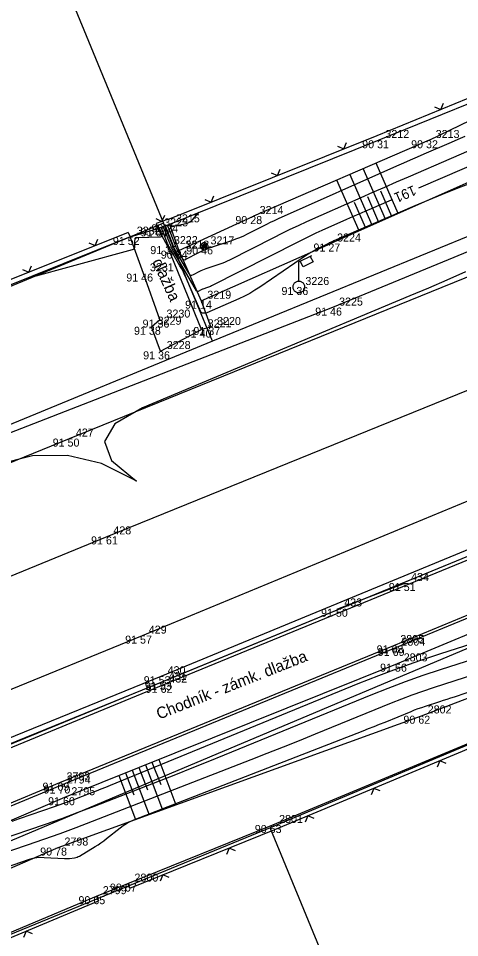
# Model space of a CAD drawing. Extents: x -711081 to -709338, y -1025122 to -1024092.
# Drawn here: x -710242.65 to -710227.21, y -1024728.91 to -1024696.77 of the extents above; entities that cross this region are included whole.
import ezdxf

# ---------------------------------------------------------------- set-up
doc = ezdxf.new("R2010")
doc.units = 0
for name, color, linetype in [('Ex_Contour Labels', 7, 'Continuous'), ('Ex_Major Contours', 7, 'Continuous'), ('Ex_Minor Contours', 7, 'Continuous'), ('Z_betonova_konstrukce', 7, 'Continuous'), ('Z_body', 7, 'Continuous'), ('Z_body_cisla', 7, 'Continuous'), ('Z_body_vysky_redukovane', 7, 'Continuous'), ('Z_chodnik', 7, 'Continuous'), ('Z_hrany_paty', 7, 'Continuous'), ('Z_katastr_hranice', 7, 'Continuous'), ('Z_komunikace', 7, 'Continuous'), ('Z_komunikace_osa', 7, 'Continuous'), ('Z_obruba', 7, 'Continuous'), ('Z_ploty', 7, 'Continuous'), ('Z_ploty_znacky', 7, 'Continuous'), ('Z_popisy', 7, 'Continuous'), ('Z_rozhranni', 7, 'Continuous'), ('Z_site_vo_znaky', 7, 'Continuous'), ('Z_sloupy', 7, 'Continuous'), ('Z_technicke_srafy', 7, 'Continuous'), ('Z_vdz12_plna', 7, 'Continuous'), ('Z_vdz25_plna', 7, 'Continuous'), ('Z_vstupy', 7, 'Continuous'), ('Z_zlabek', 7, 'Continuous')]:
    doc.layers.add(name, color=color, linetype=linetype)

# ---------------------------------------------------------------- blocks, each defined once
blk = doc.blocks.new('POINT_DISPLAY')
blk.add_line((0, 0), (0, 0))
blk = doc.blocks.new('Z212')
for p, q in [((-0.17, 0.17), (0, 0)), ((0, 0), (0.17, 0.17))]:
    blk.add_line(p, q)
blk = doc.blocks.new('Z13')
for p, q in [((0, 0.88), (0.45, 1.1)), ((0.4, 1.07), (0.5, 0.88)), ((0, 0.2), (0, 0.88)), ((0.15, 0.7), (0.05, 0.9)), ((0.5, 0.88), (0.15, 0.7)), ((-0.2, 0.05), (-0.15, 0.15)), ((-0.2, -0.05), (-0.2, 0.05)), ((-0.15, 0.15), (-0.05, 0.2)), ((-0.05, 0.2), (0.05, 0.2)), ((0.05, 0.2), (0.15, 0.15)), ((0.15, 0.15), (0.2, 0.05)), ((0.2, 0.05), (0.2, -0.05)), ((-0.15, -0.15), (-0.2, -0.05)), ((-0.05, -0.2), (-0.15, -0.15)), ((0.05, -0.2), (-0.05, -0.2)), ((0.15, -0.15), (0.05, -0.2)), ((0.2, -0.05), (0.15, -0.15))]:
    blk.add_line(p, q)
blk = doc.blocks.new('Z601')
for p, q in [((-0.13, 0.03), (-0.1, 0.08)), ((-0.13, -0.03), (-0.13, 0.03)), ((-0.1, 0.08), (-0.08, 0.1)), ((-0.08, 0.1), (-0.03, 0.13)), ((-0.08, 0.05), (-0.08, -0.05)), ((-0.03, 0.13), (0.03, 0.13)), ((-0.03, -0.08), (-0.03, 0.08)), ((-0.03, 0.08), (0.03, 0.08)), ((0.03, 0.13), (0.08, 0.1)), ((0.03, 0.08), (0.03, -0.08)), ((0.08, 0.1), (0.1, 0.08)), ((0.08, -0.05), (0.08, 0.05)), ((0.1, 0.08), (0.13, 0.03)), ((0.13, 0.03), (0.13, -0.03)), ((-0.1, -0.08), (-0.13, -0.03)), ((-0.08, -0.1), (-0.1, -0.08)), ((-0.08, -0.05), (-0.03, -0.08)), ((-0.03, -0.13), (-0.08, -0.1)), ((0.03, -0.13), (-0.03, -0.13)), ((0.03, -0.08), (0.08, -0.05)), ((0.08, -0.1), (0.03, -0.13)), ((0.1, -0.08), (0.08, -0.1)), ((0.13, -0.03), (0.1, -0.08))]:
    blk.add_line(p, q)

msp = doc.modelspace()

# ---------------------------------------------------------------- linework, layer by layer
at = {"layer": 'Ex_Major Contours'}
for points in [[(-710223.86, -1024700.64), (-710228.65, -1024702.71)], [(-710229.614, -1024703.126), (-710230.311, -1024703.428), (-710230.527, -1024703.521), (-710230.742, -1024703.615), (-710230.957, -1024703.71), (-710231.172, -1024703.805), (-710232.03, -1024704.187), (-710232.244, -1024704.284), (-710232.456, -1024704.384), (-710232.668, -1024704.486), (-710232.878, -1024704.591), (-710235.898, -1024706.125), (-710235.93, -1024706.141), (-710235.963, -1024706.156), (-710235.997, -1024706.169), (-710236.031, -1024706.181), (-710236.195, -1024706.235), (-710236.216, -1024706.242), (-710236.237, -1024706.251), (-710236.257, -1024706.26), (-710236.277, -1024706.27), (-710236.357, -1024706.313), (-710236.376, -1024706.319), (-710236.392, -1024706.319), (-710236.407, -1024706.31), (-710236.419, -1024706.295), (-710237.255, -1024704.854), (-710237.274, -1024704.819), (-710237.292, -1024704.784), (-710237.309, -1024704.748), (-710237.324, -1024704.712), (-710237.382, -1024704.564), (-710237.411, -1024704.49), (-710237.44, -1024704.417), (-710237.587, -1024704.046)], [(-710226.653, -1024719.698), (-710228.144, -1024720.176), (-710228.515, -1024720.299), (-710228.884, -1024720.429), (-710229.251, -1024720.566), (-710229.614, -1024720.711), (-710232.264, -1024721.795), (-710232.827, -1024722.024), (-710233.391, -1024722.25), (-710233.956, -1024722.474), (-710234.522, -1024722.695), (-710240.074, -1024724.851), (-710240.637, -1024725.066), (-710241.203, -1024725.276), (-710241.771, -1024725.479), (-710242.341, -1024725.675), (-710244.889, -1024726.54)]]:
    msp.add_lwpolyline(points, dxfattribs=at)
at = {"layer": 'Ex_Minor Contours'}
for points in [[(-710237.444, -1024703.996), (-710237.392, -1024704.129), (-710237.369, -1024704.186), (-710237.142, -1024704.764), (-710237.121, -1024704.814), (-710237.098, -1024704.863), (-710237.074, -1024704.911), (-710237.047, -1024704.958), (-710236.938, -1024705.146), (-710236.909, -1024705.184), (-710236.874, -1024705.204), (-710236.834, -1024705.205), (-710236.788, -1024705.189), (-710236.338, -1024704.949), (-710236.247, -1024704.902), (-710236.153, -1024704.86), (-710236.058, -1024704.822), (-710235.961, -1024704.787), (-710235.183, -1024704.531), (-710235.042, -1024704.482), (-710234.903, -1024704.427), (-710234.765, -1024704.367), (-710234.631, -1024704.301), (-710234.095, -1024704.029), (-710233.961, -1024703.962), (-710233.826, -1024703.897), (-710233.69, -1024703.833), (-710233.554, -1024703.771), (-710229.407, -1024701.926), (-710229.169, -1024701.82), (-710228.931, -1024701.715), (-710228.693, -1024701.611), (-710228.454, -1024701.508), (-710227.498, -1024701.095), (-710227.26, -1024700.99), (-710227.023, -1024700.882)], [(-710237.516, -1024704.021), (-710237.427, -1024704.245), (-710237.398, -1024704.319), (-710237.368, -1024704.394), (-710237.248, -1024704.699), (-710237.222, -1024704.761), (-710237.194, -1024704.823), (-710237.163, -1024704.883), (-710237.13, -1024704.943), (-710236.703, -1024705.678), (-710236.669, -1024705.722), (-710236.628, -1024705.745), (-710236.582, -1024705.747), (-710236.529, -1024705.728), (-710236.308, -1024705.609), (-710236.252, -1024705.581), (-710236.195, -1024705.555), (-710236.137, -1024705.532), (-710236.078, -1024705.511), (-710235.622, -1024705.361), (-710235.527, -1024705.327), (-710235.433, -1024705.291), (-710235.341, -1024705.25), (-710235.25, -1024705.206), (-710233.715, -1024704.426), (-710233.428, -1024704.283), (-710233.14, -1024704.143), (-710232.85, -1024704.007), (-710232.558, -1024703.875), (-710230.664, -1024703.032), (-710230.25, -1024702.849), (-710229.836, -1024702.666), (-710229.422, -1024702.485), (-710229.006, -1024702.305), (-710225.996, -1024701.005)], [(-710226.849, -1024702.545), (-710227.336, -1024702.731), (-710227.819, -1024702.924), (-710228.301, -1024703.121), (-710228.78, -1024703.325), (-710231.616, -1024704.55), (-710231.648, -1024704.564), (-710231.679, -1024704.578), (-710231.743, -1024704.606), (-710231.759, -1024704.614), (-710231.775, -1024704.621), (-710231.79, -1024704.629), (-710231.806, -1024704.636), (-710232.258, -1024704.866), (-710232.337, -1024704.908), (-710232.416, -1024704.953), (-710232.492, -1024705), (-710232.568, -1024705.049), (-710234.201, -1024706.162), (-710234.378, -1024706.277), (-710234.559, -1024706.383), (-710234.746, -1024706.481), (-710234.937, -1024706.57), (-710236.061, -1024707.064), (-710236.079, -1024707.071), (-710236.098, -1024707.075), (-710236.117, -1024707.077), (-710236.137, -1024707.077), (-710236.216, -1024707.07), (-710236.234, -1024707.067), (-710236.25, -1024707.059), (-710236.262, -1024707.047), (-710236.272, -1024707.031), (-710236.77, -1024705.877), (-710236.823, -1024705.759), (-710236.88, -1024705.643), (-710236.939, -1024705.529), (-710237.002, -1024705.416), (-710237.38, -1024704.765), (-710237.386, -1024704.756), (-710237.391, -1024704.745), (-710237.395, -1024704.735), (-710237.4, -1024704.725), (-710237.429, -1024704.651), (-710237.433, -1024704.64), (-710237.659, -1024704.071)], [(-710237.373, -1024703.971), (-710237.345, -1024704.041), (-710237.34, -1024704.05), (-710237.334, -1024704.055), (-710237.325, -1024704.058), (-710237.315, -1024704.057), (-710236.749, -1024703.924), (-710236.694, -1024703.907), (-710236.644, -1024703.882), (-710236.598, -1024703.85), (-710236.557, -1024703.811), (-710236.323, -1024703.55)], [(-710237.73, -1024704.096), (-710237.637, -1024704.331), (-710237.629, -1024704.365), (-710237.635, -1024704.391), (-710237.655, -1024704.406), (-710237.69, -1024704.413), (-710238.489, -1024704.444), (-710238.531, -1024704.452), (-710238.561, -1024704.471), (-710238.579, -1024704.502), (-710238.585, -1024704.545), (-710238.584, -1024704.739), (-710238.59, -1024704.784), (-710238.607, -1024704.819), (-710238.636, -1024704.845), (-710238.677, -1024704.862), (-710242.423, -1024705.887)], [(-710227.013, -1024705.629), (-710227.657, -1024705.916), (-710228.304, -1024706.197), (-710228.953, -1024706.473), (-710238.306, -1024710.387), (-710239.281, -1024710.949), (-710239.642, -1024711.564), (-710239.389, -1024712.23), (-710238.523, -1024712.948), (-710238.579, -1024712.912), (-710239.741, -1024712.334), (-710240.936, -1024712.051), (-710242.164, -1024712.064), (-710243.424, -1024712.373)], [(-710242.874, -1024724.834), (-710242.616, -1024724.743), (-710241.389, -1024724.327), (-710241.224, -1024724.27), (-710241.059, -1024724.211), (-710240.896, -1024724.151), (-710240.733, -1024724.088), (-710240.082, -1024723.836), (-710239.919, -1024723.772), (-710239.757, -1024723.708), (-710239.595, -1024723.643), (-710239.433, -1024723.577), (-710230.758, -1024720.028), (-710230.045, -1024719.744), (-710229.326, -1024719.475), (-710228.602, -1024719.219), (-710227.873, -1024718.978), (-710223.998, -1024717.737)], [(-710248.035, -1024727.095), (-710242.285, -1024725.144), (-710241.708, -1024724.944), (-710241.133, -1024724.739), (-710240.56, -1024724.527), (-710239.989, -1024724.309), (-710237.712, -1024723.424), (-710237.143, -1024723.202), (-710236.575, -1024722.977), (-710236.008, -1024722.75), (-710235.442, -1024722.52), (-710230.314, -1024720.422), (-710229.711, -1024720.182), (-710229.104, -1024719.954), (-710228.493, -1024719.738), (-710227.877, -1024719.535), (-710224.638, -1024718.498)], [(-710248.72, -1024728.404), (-710242.261, -1024726.171), (-710242.135, -1024726.134), (-710242.006, -1024726.111), (-710241.877, -1024726.1), (-710241.745, -1024726.102), (-710241.04, -1024726.147), (-710240.996, -1024726.148), (-710240.951, -1024726.148), (-710240.906, -1024726.145), (-710240.862, -1024726.14), (-710240.684, -1024726.116), (-710240.64, -1024726.108), (-710240.598, -1024726.095), (-710240.557, -1024726.078), (-710240.517, -1024726.057), (-710239.967, -1024725.727), (-710239.864, -1024725.663), (-710239.763, -1024725.595), (-710239.664, -1024725.524), (-710239.568, -1024725.449), (-710239.097, -1024725.072), (-710238.984, -1024724.989), (-710238.866, -1024724.914), (-710238.743, -1024724.849), (-710238.614, -1024724.793), (-710230.593, -1024721.679), (-710230.399, -1024721.603), (-710230.206, -1024721.526), (-710230.013, -1024721.449), (-710229.821, -1024721.371), (-710228.914, -1024721), (-710228.79, -1024720.95), (-710228.664, -1024720.903), (-710228.538, -1024720.859), (-710228.411, -1024720.817), (-710227.901, -1024720.653), (-710227.774, -1024720.612), (-710227.646, -1024720.571), (-710227.519, -1024720.528), (-710227.393, -1024720.485), (-710222.088, -1024718.677)]]:
    msp.add_lwpolyline(points, dxfattribs=at)
at = {"layer": 'Z_betonova_konstrukce'}
for p, q in [((-710237.77, -1024704.11), (-710237.43, -1024704.73)), ((-710237.37, -1024703.97), (-710237.04, -1024704.89)), ((-710236.25, -1024707.65), (-710237.43, -1024704.73)), ((-710237.04, -1024704.89), (-710236.26, -1024706.64)), ((-710236.26, -1024706.64), (-710235.92, -1024707.56)), ((-710235.92, -1024707.56), (-710236.25, -1024707.65))]:
    msp.add_line(p, q, dxfattribs=at)
at = {"layer": 'Z_chodnik'}
for p, q in [((-710229.51, -1024718.69), (-710213.59, -1024712.14)), ((-710241.2, -1024723.49), (-710229.51, -1024718.69)), ((-710252.64, -1024728.21), (-710241.2, -1024723.49))]:
    msp.add_line(p, q, dxfattribs=at)
at = {"layer": 'Z_hrany_paty'}
for p, q in [((-710228.28, -1024701.03), (-710222.83, -1024698.38)), ((-710221.98, -1024700.32), (-710231.72, -1024704.64)), ((-710228.28, -1024701.03), (-710234.43, -1024703.68)), ((-710237.04, -1024704.89), (-710234.43, -1024703.68)), ((-710236.26, -1024706.64), (-710231.72, -1024704.64)), ((-710229.39, -1024719.33), (-710213.3, -1024712.62)), ((-710228.55, -1024721.15), (-710221.89, -1024718.63)), ((-710241.03, -1024724), (-710229.39, -1024719.33)), ((-710241.26, -1024725.76), (-710228.55, -1024721.15)), ((-710250.53, -1024728.06), (-710241.03, -1024724)), ((-710248.26, -1024728.79), (-710241.26, -1024725.76))]:
    msp.add_line(p, q, dxfattribs=at)
at = {"layer": 'Z_katastr_hranice'}
for p, q in [((-710154.63, -1024688.37), (-710250.66, -1024728.78)), ((-710240.27, -1024721.05), (-710173.64, -1024693.67)), ((-710241.34, -1024694.81), (-710237.57, -1024703.93)), ((-710203.6, -1024694.8), (-710235.86, -1024708.06)), ((-710237.57, -1024703.93), (-710272.7, -1024718.41)), ((-710235.86, -1024708.06), (-710237.57, -1024703.93)), ((-710235.86, -1024708.06), (-710255.02, -1024715.93)), ((-710217.97, -1024718.42), (-710233.84, -1024725.07)), ((-710287.83, -1024740.6), (-710240.27, -1024721.05)), ((-710233.84, -1024725.07), (-710249.43, -1024731.47)), ((-710218.68, -1024761.93), (-710233.84, -1024725.07))]:
    msp.add_line(p, q, dxfattribs=at)
at = {"layer": 'Z_komunikace'}
for p, q in [((-710240.87, -1024711.46), (-710226.65, -1024705.69)), ((-710253.95, -1024716.77), (-710240.87, -1024711.46)), ((-710237.62, -1024719.97), (-710223.73, -1024714.25)), ((-710249.44, -1024724.77), (-710237.62, -1024719.97))]:
    msp.add_line(p, q, dxfattribs=at)
at = {"layer": 'Z_komunikace_osa'}
for p, q in [((-710239.55, -1024714.88), (-710225.47, -1024709.17)), ((-710252.07, -1024720.03), (-710239.55, -1024714.88))]:
    msp.add_line(p, q, dxfattribs=at)
at = {"layer": 'Z_obruba'}
for p, q in [((-710229.47, -1024718.78), (-710213.52, -1024712.2)), ((-710237.59, -1024720.07), (-710223.69, -1024714.37)), ((-710241.19, -1024723.59), (-710229.47, -1024718.78)), ((-710249.36, -1024724.91), (-710237.59, -1024720.07)), ((-710252.56, -1024728.26), (-710241.19, -1024723.59))]:
    msp.add_line(p, q, dxfattribs=at)
at = {"layer": 'Z_ploty'}
for p, q in [((-710222.09, -1024697.6), (-710230.11, -1024700.87)), ((-710222.02, -1024697.76), (-710230.04, -1024701.03)), ((-710230.11, -1024700.87), (-710237.44, -1024703.81)), ((-710230.04, -1024701.03), (-710237.37, -1024703.97)), ((-710237.43, -1024703.8), (-710237.83, -1024703.94)), ((-710237.83, -1024703.94), (-710237.77, -1024704.11)), ((-710237.37, -1024703.97), (-710237.77, -1024704.11)), ((-710238.81, -1024704.25), (-710249.86, -1024708.68)), ((-710238.74, -1024704.41), (-710249.79, -1024708.84)), ((-710238.81, -1024704.25), (-710238.74, -1024704.41)), ((-710233.75, -1024724.97), (-710221.62, -1024719.91)), ((-710233.68, -1024725.13), (-710221.55, -1024720.07)), ((-710238.82, -1024727.02), (-710233.75, -1024724.97)), ((-710238.75, -1024727.18), (-710233.68, -1024725.13)), ((-710238.82, -1024727.02), (-710238.75, -1024727.18)), ((-710250.52, -1024731.9), (-710239.92, -1024727.46)), ((-710239.92, -1024727.46), (-710239.85, -1024727.62)), ((-710250.45, -1024732.06), (-710239.85, -1024727.62))]:
    msp.add_line(p, q, dxfattribs=at)
at = {"layer": 'Z_rozhranni'}
for p, q in [((-710204.16, -1024695.52), (-710231.66, -1024706.88)), ((-710238.27, -1024705.69), (-710238.74, -1024704.41)), ((-710237.7, -1024707.3), (-710238.27, -1024705.69)), ((-710231.66, -1024706.88), (-710247.51, -1024713.04)), ((-710238, -1024707.55), (-710237.7, -1024707.3)), ((-710237.68, -1024708.41), (-710238, -1024707.55)), ((-710237.68, -1024708.41), (-710236.25, -1024707.65))]:
    msp.add_line(p, q, dxfattribs=at)
at = {"layer": 'Z_technicke_srafy'}
for p, q in [((-710229.36, -1024703.59), (-710230.13, -1024701.83)), ((-710229.81, -1024703.79), (-710230.59, -1024702.02)), ((-710230.73, -1024704.2), (-710231.51, -1024702.42)), ((-710230.27, -1024704), (-710231.05, -1024702.22)), ((-710229.59, -1024703.69), (-710229.97, -1024702.81)), ((-710230.04, -1024703.9), (-710230.43, -1024703.01)), ((-710230.5, -1024704.1), (-710230.89, -1024703.21)), ((-710237.74, -1024722.68), (-710237.14, -1024724.27)), ((-710238.67, -1024723.05), (-710238.08, -1024724.61)), ((-710238.44, -1024722.96), (-710238.14, -1024723.74)), ((-710238.21, -1024722.87), (-710237.61, -1024724.44)), ((-710237.98, -1024722.77), (-710237.67, -1024723.56)), ((-710239.14, -1024723.24), (-710238.55, -1024724.78)), ((-710238.9, -1024723.15), (-710238.61, -1024723.92))]:
    msp.add_line(p, q, dxfattribs=at)
at = {"layer": 'Z_vdz12_plna'}
for p, q in [((-710237.66, -1024719.77), (-710223.75, -1024714.03)), ((-710250.28, -1024724.91), (-710237.66, -1024719.77))]:
    msp.add_line(p, q, dxfattribs=at)
at = {"layer": 'Z_vdz25_plna'}
for p, q in [((-710238.31, -1024718.35), (-710224.17, -1024712.5)), ((-710250.83, -1024723.44), (-710238.31, -1024718.35))]:
    msp.add_line(p, q, dxfattribs=at)
at = {"layer": 'Z_vstupy'}
for p, q in [((-710238.74, -1024704.41), (-710237.77, -1024704.11)), ((-710239.92, -1024727.46), (-710238.82, -1024727.02))]:
    msp.add_line(p, q, dxfattribs=at)
at = {"layer": 'Z_zlabek'}
msp.add_line((-710231.48, -1024717.41), (-710229.13, -1024716.51), dxfattribs=at)

# ---------------------------------------------------------------- block references
at = {"layer": 'Z_body'}
for p in [(-710230.04, -1024701.03), (-710228.28, -1024701.03), (-710234.43, -1024703.68), (-710237.77, -1024704.11), (-710237.37, -1024703.97), (-710238.74, -1024704.41), (-710237.43, -1024704.73), (-710236.15, -1024704.74), (-710231.72, -1024704.64), (-710237.04, -1024704.89), (-710238.27, -1024705.69), (-710232.84, -1024706.16), (-710236.26, -1024706.64), (-710231.66, -1024706.88), (-710237.7, -1024707.3), (-710238, -1024707.55), (-710236.25, -1024707.65), (-710235.92, -1024707.56), (-710237.68, -1024708.41), (-710240.87, -1024711.46), (-710239.55, -1024714.88), (-710229.13, -1024716.51), (-710231.48, -1024717.41), (-710238.31, -1024718.35), (-710229.51, -1024718.69), (-710229.47, -1024718.78), (-710229.39, -1024719.33), (-710237.66, -1024719.77), (-710237.62, -1024719.97), (-710237.59, -1024720.07), (-710228.55, -1024721.15), (-710241.2, -1024723.49), (-710241.19, -1024723.59), (-710241.03, -1024724), (-710233.75, -1024724.97), (-710241.26, -1024725.76), (-710238.82, -1024727.02), (-710239.92, -1024727.46)]:
    msp.add_blockref('POINT_DISPLAY', p, dxfattribs=at)
at = {"layer": 'Z_ploty_znacky'}
for p, rotation in [((-710227.87, -1024699.96), 22.2), ((-710231.27, -1024701.33), 21.9), ((-710233.59, -1024702.26), 21.9), ((-710235.91, -1024703.19), 21.9), ((-710237.63, -1024703.87), 19.300000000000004), ((-710239.97, -1024704.71), 21.8), ((-710242.29, -1024705.64), 21.8), ((-710227.91, -1024722.73), -157.40000000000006), ((-710230.22, -1024723.69), -157.40000000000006), ((-710232.53, -1024724.65), -157.40000000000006), ((-710235.28, -1024725.78), -158.00000000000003), ((-710237.6, -1024726.71), -158.00000000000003), ((-710242.38, -1024728.68), -157.30000000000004)]:
    msp.add_blockref('Z212', p, dxfattribs=dict(at, rotation=rotation))
at = {"layer": 'Z_site_vo_znaky'}
msp.add_blockref('Z13', (-710232.84, -1024706.16), dxfattribs=at)
at = {"layer": 'Z_sloupy'}
msp.add_blockref('Z601', (-710236.15, -1024704.74), dxfattribs=at)

# ---------------------------------------------------------------- texts
at = {"layer": 'Ex_Contour Labels'}
msp.add_text('191', height=0.35, rotation=203.367, dxfattribs=at).set_placement((-710228.827, -1024702.596))
at = {"layer": 'Z_body_cisla'}
for s, p in [('3212', (-710229.81, -1024700.95)), ('3213', (-710228.05, -1024700.95)), ('3214', (-710234.21, -1024703.61)), ('3223', (-710237.55, -1024704.04)), ('3215', (-710237.14, -1024703.9)), ('3232', (-710238.51, -1024704.33)), ('3222', (-710237.21, -1024704.66)), ('3217', (-710235.93, -1024704.67)), ('3224', (-710231.5, -1024704.57)), ('3218', (-710236.81, -1024704.82)), ('3231', (-710238.05, -1024705.61)), ('3226', (-710232.61, -1024706.09)), ('3219', (-710236.04, -1024706.57)), ('3225', (-710231.43, -1024706.81)), ('3230', (-710237.47, -1024707.23)), ('3229', (-710237.78, -1024707.48)), ('3221', (-710236.03, -1024707.57)), ('3220', (-710235.7, -1024707.49)), ('3228', (-710237.46, -1024708.33)), ('427', (-710240.64, -1024711.39)), ('428', (-710239.33, -1024714.81)), ('434', (-710228.91, -1024716.44)), ('433', (-710231.25, -1024717.33)), ('429', (-710238.09, -1024718.28)), ('2805', (-710229.29, -1024718.61)), ('2804', (-710229.25, -1024718.7)), ('2803', (-710229.17, -1024719.25)), ('430', (-710237.43, -1024719.7)), ('431', (-710237.39, -1024719.9)), ('432', (-710237.37, -1024719.99)), ('2802', (-710228.33, -1024721.07)), ('2793', (-710240.97, -1024723.41)), ('2794', (-710240.96, -1024723.52)), ('2795', (-710240.8, -1024723.93)), ('2801', (-710233.53, -1024724.9)), ('2798', (-710241.04, -1024725.69)), ('2800', (-710238.59, -1024726.95)), ('2799', (-710239.7, -1024727.39))]:
    msp.add_text(s, height=0.28, dxfattribs=at).set_placement(p)
at = {"layer": 'Z_body_vysky_redukovane'}
for s, p in [('90 31', (-710230.623, -1024701.31)), ('90 32', (-710228.91, -1024701.31)), ('90 28', (-710235.06, -1024703.96)), ('91 64', (-710238.377, -1024704.39)), ('90 24', (-710238, -1024704.25)), ('91 52', (-710239.347, -1024704.69)), ('91 35', (-710238.037, -1024705.01)), ('90 46', (-710236.78, -1024705.02)), ('91 27', (-710232.327, -1024704.92)), ('90 34', (-710237.67, -1024705.17)), ('91 46', (-710238.877, -1024705.97)), ('91 36', (-710233.447, -1024706.44)), ('91 14', (-710236.82, -1024706.92)), ('91 46', (-710232.267, -1024707.16)), ('91 36', (-710238.307, -1024707.58)), ('91 38', (-710238.607, -1024707.83)), ('91 40', (-710236.833, -1024707.93)), ('91 37', (-710236.527, -1024707.84)), ('91 36', (-710238.287, -1024708.69)), ('91 50', (-710241.453, -1024711.74)), ('91 61', (-710240.11, -1024715.16)), ('91 51', (-710229.69, -1024716.79)), ('91 50', (-710232.063, -1024717.69)), ('91 57', (-710238.917, -1024718.63)), ('91 68', (-710230.117, -1024718.97)), ('91 69', (-710230.077, -1024719.06)), ('91 56', (-710229.997, -1024719.61)), ('91 53', (-710238.267, -1024720.05)), ('91 53', (-710238.227, -1024720.25)), ('91 62', (-710238.197, -1024720.35)), ('90 62', (-710229.18, -1024721.43)), ('91 69', (-710241.807, -1024723.77)), ('91 70', (-710241.773, -1024723.87)), ('91 60', (-710241.613, -1024724.28)), ('90 63', (-710234.38, -1024725.25)), ('90 78', (-710241.89, -1024726.04)), ('90 67', (-710239.45, -1024727.3)), ('90 65', (-710240.55, -1024727.74))]:
    msp.add_text(s, height=0.28, dxfattribs=at).set_placement(p)
at = {"layer": 'Z_popisy'}
for s, rotation, p in [('dlažba', 294.3, (-710237.98, -1024705.27)), ('Chodník - zámk. dlažba', 21.6, (-710237.73, -1024721.29))]:
    msp.add_text(s, height=0.4, rotation=rotation, dxfattribs=at).set_placement(p)

doc.saveas('drawing.dxf')
